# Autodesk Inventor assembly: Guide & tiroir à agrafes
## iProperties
Author: Flavien MARTY
Shininess: 21.0
PropertySet Name: _Private Model Information
Created: 2001-10
Part Number: Guide & tiroir à agrafes
Document SubType Name: Assemblage
Designer: Flavien MARTY
Control State: 0
Master: False
Checked Out: False
PropertySet Name: Design Tracking Control
Density: 0.0
Volumn: 0.0
Area: 0.0
PropertySet Name: Model Information
